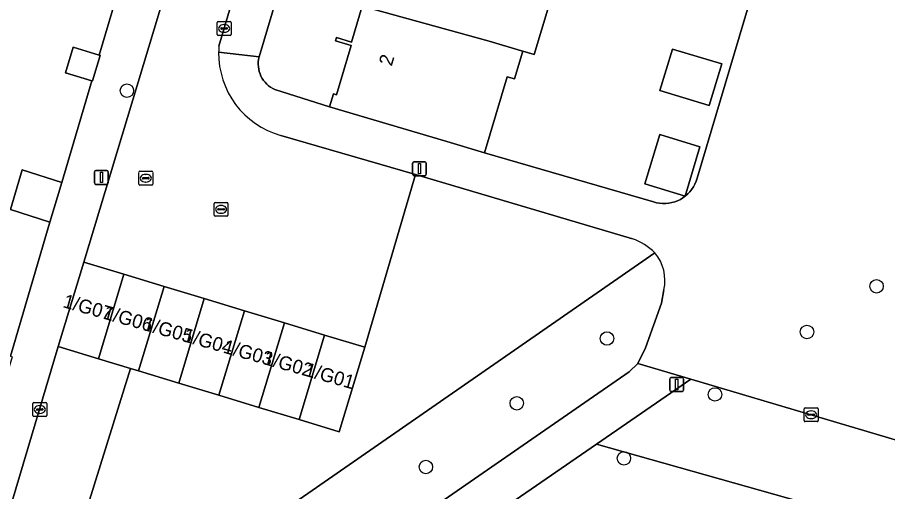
# Model space of a CAD drawing. Extents: x 162184 to 163154, y 385507 to 386516.
# Drawn here: x 162712.4 to 162775.6, y 386055 to 386089.3 of the extents above; entities that cross this region are included whole.
import ezdxf

# ---------------------------------------------------------------- set-up
doc = ezdxf.new("R2010")
doc.units = 0
for name, color, linetype in [('IMGEO_Boom', 7, 'Continuous'), ('IMGEO_Erf', 7, 'Continuous'), ('IMGEO_Groenvoorziening', 7, 'Continuous'), ('IMGEO_Kolk', 7, 'Continuous'), ('IMGEO_Lichtmast', 7, 'Continuous'), ('IMGEO_Pand', 7, 'Continuous'), ('IMGEO_Pand_nummerreeks', 7, 'Continuous'), ('IMGEO_Rijbaan_lokaal_open', 7, 'Continuous'), ('IMGEO_Rioolput', 7, 'Continuous'), ('IMGEO_Voetpad_halfverhard', 7, 'Continuous'), ('IMGEO_Voetpad_open', 7, 'Continuous')]:
    doc.layers.add(name, color=color, linetype=linetype)

msp = doc.modelspace()

# ---------------------------------------------------------------- linework, layer by layer
at = {"layer": 'IMGEO_Boom'}
for centre in [(162720.367, 386084.025), (162774.757, 386069.847), (162769.709, 386066.539), (162755.197, 386066.062), (162763.033, 386062.009), (162748.653, 386061.368), (162756.426, 386057.379), (162742.059, 386056.751)]:
    msp.add_circle(centre, 0.489, dxfattribs=at)
at = {"layer": 'IMGEO_Erf'}
for points in [[(162748.726, 386149.462), (162729.962, 386086.464), (162729.923, 386086.29), (162729.9, 386086.113), (162729.893, 386085.934), (162729.902, 386085.756), (162729.927, 386085.579), (162729.967, 386085.406), (162730.023, 386085.236), (162730.093, 386085.072), (162730.178, 386084.915), (162730.277, 386084.766), (162730.389, 386084.627), (162730.512, 386084.498), (162730.647, 386084.381), (162730.791, 386084.277), (162730.945, 386084.185), (162731.096, 386084.112), (162735.074, 386082.862), (162735.351, 386083.791), (162735.572, 386083.726), (162736.634, 386087.29), (162735.49, 386087.63), (162735.563, 386087.875), (162736.667, 386087.546), (162737.443, 386090.149)], [(162751.517, 386091.957), (162749.91, 386086.652), (162749.086, 386086.882), (162748.488, 386084.875), (162747.961, 386085.032), (162746.315, 386079.512), (162758.579, 386075.961), (162758.794, 386075.903), (162759.013, 386075.865), (162759.235, 386075.846), (162759.457, 386075.847), (162759.679, 386075.868), (162759.898, 386075.909), (162760.112, 386075.969), (162760.32, 386076.049), (162760.52, 386076.146), (162760.711, 386076.261), (162760.89, 386076.392), (162761.057, 386076.539), (162761.211, 386076.7), (162761.349, 386076.875), (162761.471, 386077.061), (162761.576, 386077.257), (162761.663, 386077.462), (162761.733, 386077.677), (162769.446, 386103.583)], [(162714.781, 386074.502), (162711.92, 386075.404), (162712.775, 386078.28), (162715.637, 386077.378), (162717.814, 386084.744), (162715.905, 386085.309), (162716.455, 386087.166), (162718.363, 386086.601), (162721.377, 386096.799)], [(162703.157, 386035.017), (162711.228, 386062.433), (162709.084, 386063.069), (162709.779, 386065.415), (162711.919, 386064.781), (162714.781, 386074.502)]]:
    msp.add_lwpolyline(points, dxfattribs=at)
for points in [[(162763.522, 386085.955), (162762.609, 386082.944), (162759.03, 386084.029), (162759.942, 386087.04)], [(162761.944, 386079.957), (162760.862, 386076.386), (162757.947, 386077.269), (162759.029, 386080.84)]]:
    msp.add_lwpolyline(points, close=True, dxfattribs=at)
at = {"layer": 'IMGEO_Groenvoorziening'}
for points in [[(162757.052, 386073.289), (162741.294, 386077.935), (162737.62, 386065.425), (162735.767, 386059.304), (162732.856, 386060.186), (162729.945, 386061.067), (162727.034, 386061.948), (162724.123, 386062.83), (162721.212, 386063.711), (162720.628, 386063.888), (162714.555, 386044.411), (162717.31, 386043.615), (162758.68, 386072.273)], [(162758.68, 386072.273), (162717.31, 386043.615), (162714.555, 386044.411), (162720.628, 386063.888), (162718.301, 386064.593), (162715.39, 386065.474), (162705.881, 386033.637)], [(162756.796, 386063.642), (162757.426, 386064.259), (162757.996, 386065.377), (162759.153, 386068.627), (162759.328, 386069.587)], [(162707.08, 386031.526), (162707.413, 386031.401), (162707.756, 386031.307), (162708.106, 386031.243), (162708.46, 386031.211), (162708.816, 386031.211), (162709.17, 386031.242), (162709.52, 386031.305), (162709.863, 386031.4), (162710.196, 386031.524), (162710.517, 386031.677), (162710.65, 386031.752), (162756.796, 386063.642)]]:
    msp.add_lwpolyline(points, dxfattribs=at)
for points in [[(162784.669, 386056.18), (162761.276, 386063.106), (162754.435, 386058.403), (162786.142, 386049.469), (162786.962, 386052.186), (162787.099, 386053.344), (162787.091, 386053.575), (162787.062, 386053.805), (162787.012, 386054.031), (162786.943, 386054.251), (162786.854, 386054.465), (162786.746, 386054.67), (162786.621, 386054.864), (162786.479, 386055.046), (162786.445, 386055.085), (162785.618, 386055.732)], [(162786.142, 386049.469), (162754.435, 386058.403), (162737.255, 386046.591), (162738.48, 386044.772), (162728.34, 386033.438), (162739.19, 386030.113), (162741.29, 386037.011), (162742.152, 386036.767), (162746.108, 386049.727), (162752.73, 386047.547), (162754.611, 386053.744), (162757.507, 386052.864), (162760.403, 386051.985), (162763.299, 386051.105), (162766.195, 386050.226), (162769.092, 386049.346), (162771.988, 386048.466), (162774.884, 386047.587), (162777.78, 386046.707), (162780.676, 386045.828), (162783.572, 386044.948), (162781.69, 386038.751), (162782.799, 386038.397)]]:
    msp.add_lwpolyline(points, close=True, dxfattribs=at)
for centre, radius, start, end in [((162755.533, 386069.043), 4.509, 45.74708, 70.31811), ((162756.263, 386070.269), 3.14, 347.45747, 39.6695)]:
    msp.add_arc(centre, radius, start, end, dxfattribs=at)
at = {"layer": 'IMGEO_Kolk'}
for p, q in [((162726.92, 386088.104), (162726.92, 386088.956)), ((162726.995, 386089.03), (162727.847, 386089.03)), ((162727.408, 386088.81), (162727.433, 386088.81)), ((162727.921, 386088.956), (162727.921, 386088.104)), ((162727.179, 386088.524), (162727.179, 386088.536)), ((162727.617, 386088.487), (162727.219, 386088.487)), ((162727.222, 386088.573), (162727.62, 386088.573)), ((162727.431, 386088.25), (162727.406, 386088.25)), ((162727.663, 386088.536), (162727.663, 386088.524)), ((162727.847, 386088.03), (162726.995, 386088.03)), ((162726.698, 386074.995), (162726.698, 386075.847)), ((162726.773, 386075.921), (162727.625, 386075.921)), ((162727.186, 386075.701), (162727.211, 386075.701)), ((162727.699, 386075.847), (162727.699, 386074.995)), ((162727.625, 386074.921), (162726.773, 386074.921)), ((162726.957, 386075.415), (162726.957, 386075.427)), ((162727.395, 386075.378), (162726.997, 386075.378)), ((162727, 386075.464), (162727.398, 386075.464)), ((162727.209, 386075.141), (162727.184, 386075.141)), ((162727.441, 386075.427), (162727.441, 386075.415)), ((162713.547, 386060.492), (162713.547, 386061.344)), ((162713.622, 386061.418), (162714.474, 386061.418)), ((162714.035, 386061.198), (162714.06, 386061.198)), ((162714.548, 386061.344), (162714.548, 386060.492)), ((162769.585, 386061.038), (162770.437, 386061.038)), ((162714.474, 386060.418), (162713.622, 386060.418)), ((162713.806, 386060.912), (162713.806, 386060.924)), ((162714.244, 386060.875), (162713.846, 386060.875)), ((162713.849, 386060.961), (162714.247, 386060.961)), ((162714.058, 386060.638), (162714.033, 386060.638)), ((162714.29, 386060.924), (162714.29, 386060.912)), ((162769.51, 386060.112), (162769.51, 386060.964)), ((162769.769, 386060.532), (162769.769, 386060.544)), ((162770.207, 386060.495), (162769.809, 386060.495)), ((162769.812, 386060.581), (162770.21, 386060.581)), ((162769.998, 386060.818), (162770.023, 386060.818)), ((162770.253, 386060.544), (162770.253, 386060.532)), ((162770.511, 386060.964), (162770.511, 386060.112)), ((162770.437, 386060.038), (162769.585, 386060.038)), ((162770.021, 386060.258), (162769.996, 386060.258))]:
    msp.add_line(p, q, dxfattribs=at)
for points in [[(162726.92, 386088.104), (162726.92, 386088.956)], [(162726.995, 386089.03), (162727.847, 386089.03)], [(162727.921, 386088.956), (162727.921, 386088.104)], [(162727.847, 386088.03), (162726.995, 386088.03)], [(162726.698, 386074.995), (162726.698, 386075.847)], [(162726.773, 386075.921), (162727.625, 386075.921)], [(162727.699, 386075.847), (162727.699, 386074.995)], [(162727.625, 386074.921), (162726.773, 386074.921)], [(162713.547, 386060.492), (162713.547, 386061.344)], [(162713.622, 386061.418), (162714.474, 386061.418)], [(162714.548, 386061.344), (162714.548, 386060.492)], [(162769.585, 386061.038), (162770.437, 386061.038)], [(162714.474, 386060.418), (162713.622, 386060.418)], [(162769.51, 386060.112), (162769.51, 386060.964)], [(162770.511, 386060.964), (162770.511, 386060.112)], [(162770.437, 386060.038), (162769.585, 386060.038)]]:
    msp.add_lwpolyline(points, dxfattribs=at)
for centre, radius, start, end in [((162726.997, 386088.954), 0.0765, 91.55205, 178.44795), ((162726.997, 386088.954), 0.0765, 91.55205, 178.44795), ((162727.845, 386088.954), 0.0765, 1.55205, 88.44795), ((162727.845, 386088.954), 0.0765, 1.55205, 88.44795), ((162727.219, 386088.533), 0.0403, 85.87752, 175.75265), ((162727.216, 386088.523), 0.0366, 178.93798, 274.71019), ((162727.62, 386088.53), 0.043, 264.86636, 352.45326), ((162727.624, 386088.535), 0.0386, 1.73085, 96.63898), ((162726.997, 386088.106), 0.0765, 181.55205, 268.44795), ((162726.997, 386088.106), 0.0765, 181.55205, 268.44795), ((162727.845, 386088.106), 0.0765, 271.55205, 358.44795), ((162727.845, 386088.106), 0.0765, 271.55205, 358.44795), ((162726.775, 386075.845), 0.0765, 91.55205, 178.44795), ((162726.775, 386075.845), 0.0765, 91.55205, 178.44795), ((162727.623, 386075.845), 0.0765, 1.55205, 88.44795), ((162727.623, 386075.845), 0.0765, 1.55205, 88.44795), ((162726.775, 386074.997), 0.0765, 181.55205, 268.44795), ((162726.775, 386074.997), 0.0765, 181.55205, 268.44795), ((162726.997, 386075.424), 0.0403, 85.87752, 175.75265), ((162726.994, 386075.414), 0.0366, 178.93798, 274.71019), ((162727.398, 386075.421), 0.043, 264.86636, 352.45326), ((162727.402, 386075.426), 0.0386, 1.73085, 96.63898), ((162727.623, 386074.997), 0.0765, 271.55205, 358.44795), ((162727.623, 386074.997), 0.0765, 271.55205, 358.44795), ((162713.624, 386061.342), 0.0765, 91.55205, 178.44795), ((162713.624, 386061.342), 0.0765, 91.55205, 178.44795), ((162714.472, 386061.342), 0.0765, 1.55205, 88.44795), ((162714.472, 386061.342), 0.0765, 1.55205, 88.44795), ((162769.587, 386060.962), 0.0765, 91.55205, 178.44795), ((162769.587, 386060.962), 0.0765, 91.55205, 178.44795), ((162770.435, 386060.962), 0.0765, 1.55205, 88.44795), ((162770.435, 386060.962), 0.0765, 1.55205, 88.44795), ((162713.624, 386060.494), 0.0765, 181.55205, 268.44795), ((162713.624, 386060.494), 0.0765, 181.55205, 268.44795), ((162713.846, 386060.921), 0.0403, 85.87752, 175.75265), ((162713.843, 386060.911), 0.0366, 178.93798, 274.71019), ((162714.247, 386060.918), 0.043, 264.86636, 352.45326), ((162714.251, 386060.923), 0.0386, 1.73085, 96.63898), ((162714.472, 386060.494), 0.0765, 271.55205, 358.44795), ((162714.472, 386060.494), 0.0765, 271.55205, 358.44795), ((162769.809, 386060.541), 0.0403, 85.87752, 175.75265), ((162769.806, 386060.531), 0.0366, 178.93798, 274.71019), ((162770.21, 386060.538), 0.043, 264.86636, 352.45326), ((162770.214, 386060.543), 0.0386, 1.73085, 96.63898), ((162769.587, 386060.114), 0.0765, 181.55205, 268.44795), ((162769.587, 386060.114), 0.0765, 181.55205, 268.44795), ((162770.435, 386060.114), 0.0765, 271.55205, 358.44795), ((162770.435, 386060.114), 0.0765, 271.55205, 358.44795)]:
    msp.add_arc(centre, radius, start, end, dxfattribs=at)
for centre, major_axis, ratio, start_param, end_param in [((162727.407, 386088.53), (-0.387, 0.002), 0.722429, 4.712389, 7.853982), ((162727.432, 386088.53), (-0.39, 0.002), 0.717154, 1.570796, 4.712389), ((162727.185, 386075.421), (-0.387, 0.002), 0.722429, 4.712389, 7.853982), ((162727.21, 386075.421), (-0.39, 0.002), 0.717154, 1.570796, 4.712389), ((162714.034, 386060.918), (-0.387, 0.002), 0.722429, 4.712389, 7.853982), ((162714.059, 386060.918), (-0.39, 0.002), 0.717154, 1.570796, 4.712389), ((162769.997, 386060.538), (-0.387, 0.002), 0.722429, 4.712389, 7.853982), ((162770.022, 386060.538), (-0.39, 0.002), 0.717154, 1.570796, 4.712389)]:
    msp.add_ellipse(centre, major_axis=major_axis, ratio=ratio, start_param=start_param, end_param=end_param, dxfattribs=at)
at = {"layer": 'IMGEO_Lichtmast'}
for p, q in [((162741.095, 386077.961), (162741.095, 386078.761)), ((162741.095, 386078.761), (162741.095, 386077.961)), ((162741.195, 386078.861), (162741.985, 386078.861)), ((162741.985, 386078.861), (162741.195, 386078.861)), ((162742.085, 386078.761), (162742.085, 386077.961)), ((162742.085, 386077.961), (162742.085, 386078.761)), ((162718.02, 386077.334), (162718.02, 386078.134)), ((162718.02, 386078.134), (162718.02, 386077.334)), ((162718.12, 386078.234), (162718.91, 386078.234)), ((162718.91, 386078.234), (162718.12, 386078.234)), ((162719.01, 386078.134), (162719.01, 386077.334)), ((162719.01, 386077.334), (162719.01, 386078.134)), ((162741.985, 386077.861), (162741.195, 386077.861)), ((162741.195, 386077.861), (162741.985, 386077.861)), ((162718.91, 386077.234), (162718.12, 386077.234)), ((162718.12, 386077.234), (162718.91, 386077.234)), ((162759.76, 386062.329), (162759.76, 386063.129)), ((162759.76, 386063.129), (162759.76, 386062.329)), ((162759.86, 386063.229), (162760.65, 386063.229)), ((162760.65, 386063.229), (162759.86, 386063.229)), ((162760.75, 386063.129), (162760.75, 386062.329)), ((162760.75, 386062.329), (162760.75, 386063.129)), ((162760.65, 386062.229), (162759.86, 386062.229)), ((162759.86, 386062.229), (162760.65, 386062.229))]:
    msp.add_line(p, q, dxfattribs=at)
for points in [[(162741.515, 386078.736), (162741.665, 386078.736), (162741.665, 386077.986), (162741.515, 386077.986), (162741.515, 386078.736)], [(162718.44, 386078.109), (162718.59, 386078.109), (162718.59, 386077.359), (162718.44, 386077.359), (162718.44, 386078.109)], [(162760.18, 386063.104), (162760.33, 386063.104), (162760.33, 386062.354), (162760.18, 386062.354), (162760.18, 386063.104)]]:
    msp.add_lwpolyline(points, dxfattribs=at)
for centre, start, end in [((162741.195, 386078.761), 90, 180), ((162741.195, 386078.761), 90, 180), ((162741.985, 386078.761), 0, 90), ((162741.985, 386078.761), 360, 90), ((162718.12, 386078.134), 90, 180), ((162718.12, 386078.134), 90, 180), ((162718.91, 386078.134), 0, 90), ((162718.91, 386078.134), 360, 90), ((162741.195, 386077.961), 180, 270), ((162741.195, 386077.961), 180, 270), ((162741.985, 386077.961), 270, 0), ((162741.985, 386077.961), 270, 0), ((162718.12, 386077.334), 180, 270), ((162718.12, 386077.334), 180, 270), ((162718.91, 386077.334), 270, 0), ((162718.91, 386077.334), 270, 0), ((162759.86, 386063.129), 90, 180), ((162759.86, 386063.129), 90, 180), ((162760.65, 386063.129), 0, 90), ((162760.65, 386063.129), 360, 90), ((162759.86, 386062.329), 180, 270), ((162759.86, 386062.329), 180, 270), ((162760.65, 386062.329), 270, 0), ((162760.65, 386062.329), 270, 0)]:
    msp.add_arc(centre, 0.1, start, end, dxfattribs=at)
at = {"layer": 'IMGEO_Pand'}
for points in [[(162754.46, 386093.36), (162752.141, 386094.051), (162747.794, 386095.346), (162740.655, 386097.299), (162738.746, 386090.892), (162738.575, 386090.943), (162738.336, 386090.144), (162736.371, 386090.729), (162736.3, 386090.49), (162737.443, 386090.149), (162746.654, 386087.61), (162748.993, 386086.91), (162749.086, 386086.882), (162749.91, 386086.652), (162751.517, 386091.957), (162753.838, 386091.271)], [(162746.315, 386079.512), (162747.961, 386085.032), (162748.488, 386084.875), (162749.086, 386086.882), (162748.993, 386086.91), (162746.654, 386087.61), (162737.443, 386090.149), (162736.667, 386087.546), (162735.563, 386087.875), (162735.49, 386087.63), (162736.634, 386087.29), (162735.572, 386083.726), (162735.351, 386083.791), (162735.074, 386082.862), (162743.573, 386080.329)], [(162718.363, 386086.601), (162716.455, 386087.166), (162715.905, 386085.309), (162717.814, 386084.744), (162717.88, 386084.724), (162718.43, 386086.581)], [(162759.03, 386084.029), (162762.609, 386082.944), (162763.522, 386085.955), (162759.942, 386087.04)], [(162757.947, 386077.269), (162760.862, 386076.386), (162761.944, 386079.957), (162759.029, 386080.84)], [(162715.637, 386077.378), (162712.775, 386078.28), (162711.92, 386075.404), (162714.781, 386074.502)], [(162715.39, 386065.474), (162718.301, 386064.593), (162720.154, 386070.714), (162717.243, 386071.595)], [(162720.154, 386070.714), (162718.301, 386064.593), (162720.628, 386063.888), (162721.212, 386063.711), (162723.065, 386069.832)], [(162723.065, 386069.832), (162721.212, 386063.711), (162724.123, 386062.83), (162725.976, 386068.951)], [(162725.976, 386068.951), (162724.123, 386062.83), (162727.034, 386061.948), (162728.887, 386068.069)], [(162728.887, 386068.069), (162727.034, 386061.948), (162729.945, 386061.067), (162731.798, 386067.188)], [(162731.798, 386067.188), (162729.945, 386061.067), (162732.856, 386060.186), (162734.709, 386066.306)], [(162734.709, 386066.306), (162732.856, 386060.186), (162735.767, 386059.304), (162737.62, 386065.425)]]:
    msp.add_lwpolyline(points, close=True, dxfattribs=at)
at = {"layer": 'IMGEO_Rijbaan_lokaal_open'}
for points in [[(162735.486, 386115.734), (162730.846, 386117.114), (162725.891, 386100.255), (162717.243, 386071.595), (162720.154, 386070.714), (162723.065, 386069.832), (162725.976, 386068.951), (162728.887, 386068.069), (162731.798, 386067.188), (162734.709, 386066.306), (162737.62, 386065.425), (162741.294, 386077.935), (162731.535, 386080.772)], [(162727.044, 386087.256), (162730.41, 386098.664), (162735.486, 386115.734)], [(162769.446, 386103.583), (162761.733, 386077.677), (162761.663, 386077.462), (162761.576, 386077.257), (162761.471, 386077.061), (162761.349, 386076.875), (162761.211, 386076.7), (162761.057, 386076.539), (162760.89, 386076.392), (162760.711, 386076.261), (162760.52, 386076.146), (162760.32, 386076.049), (162760.112, 386075.969), (162759.898, 386075.909), (162759.679, 386075.868), (162759.457, 386075.847), (162759.235, 386075.846), (162759.013, 386075.865), (162758.794, 386075.903), (162758.579, 386075.961), (162746.315, 386079.512), (162743.573, 386080.329), (162735.074, 386082.862), (162731.096, 386084.112), (162730.945, 386084.185), (162730.791, 386084.277), (162730.647, 386084.381), (162730.512, 386084.498), (162730.389, 386084.627), (162730.277, 386084.766), (162730.178, 386084.915), (162730.093, 386085.072), (162730.023, 386085.236), (162729.967, 386085.406), (162729.927, 386085.579), (162729.902, 386085.756), (162729.893, 386085.934), (162729.9, 386086.113), (162729.923, 386086.29), (162729.962, 386086.464), (162727.023, 386086.818)], [(162731.535, 386080.772), (162741.294, 386077.935), (162757.052, 386073.289)], [(162759.328, 386069.587), (162759.153, 386068.627), (162757.996, 386065.377), (162757.426, 386064.259), (162761.276, 386063.106), (162784.669, 386056.18), (162784.356, 386059.006)]]:
    msp.add_lwpolyline(points, dxfattribs=at)
for centre, radius, start, end in [((162732.373, 386086.781), 5.35, 174.90615, 179.60394), ((162733.219, 386086.736), 6.197, 179.23909, 254.22729), ((162733.219, 386086.736), 6.197, 179.23909, 254.22729), ((162755.533, 386069.043), 4.509, 45.74708, 70.31811), ((162756.263, 386070.269), 3.14, 347.45747, 39.6695)]:
    msp.add_arc(centre, radius, start, end, dxfattribs=at)
at = {"layer": 'IMGEO_Rioolput'}
for p, q in [((162721.237, 386077.252), (162721.237, 386078.104)), ((162721.312, 386078.178), (162722.164, 386078.178)), ((162722.238, 386078.104), (162722.238, 386077.252)), ((162721.496, 386077.672), (162721.496, 386077.684)), ((162721.934, 386077.635), (162721.536, 386077.635)), ((162721.539, 386077.721), (162721.937, 386077.721)), ((162721.725, 386077.958), (162721.75, 386077.958)), ((162721.98, 386077.684), (162721.98, 386077.672)), ((162722.164, 386077.178), (162721.312, 386077.178)), ((162721.748, 386077.398), (162721.723, 386077.398))]:
    msp.add_line(p, q, dxfattribs=at)
for points in [[(162721.237, 386077.252), (162721.237, 386078.104)], [(162721.312, 386078.178), (162722.164, 386078.178)], [(162722.238, 386078.104), (162722.238, 386077.252)], [(162722.164, 386077.178), (162721.312, 386077.178)]]:
    msp.add_lwpolyline(points, dxfattribs=at)
for centre, radius, start, end in [((162721.314, 386078.102), 0.0765, 91.55205, 178.44795), ((162721.314, 386078.102), 0.0765, 91.55205, 178.44795), ((162722.162, 386078.102), 0.0765, 1.55205, 88.44795), ((162722.162, 386078.102), 0.0765, 1.55205, 88.44795), ((162721.536, 386077.681), 0.0403, 85.87752, 175.75265), ((162721.533, 386077.671), 0.0366, 178.93798, 274.71019), ((162721.937, 386077.678), 0.043, 264.86636, 352.45326), ((162721.941, 386077.683), 0.0386, 1.73085, 96.63898), ((162721.314, 386077.254), 0.0765, 181.55205, 268.44795), ((162721.314, 386077.254), 0.0765, 181.55205, 268.44795), ((162722.162, 386077.254), 0.0765, 271.55205, 358.44795), ((162722.162, 386077.254), 0.0765, 271.55205, 358.44795)]:
    msp.add_arc(centre, radius, start, end, dxfattribs=at)
for centre, major_axis, ratio, start_param, end_param in [((162721.724, 386077.678), (-0.387, 0.002), 0.722429, 4.712389, 7.853982), ((162721.749, 386077.678), (-0.39, 0.002), 0.717154, 1.570796, 4.712389)]:
    msp.add_ellipse(centre, major_axis=major_axis, ratio=ratio, start_param=start_param, end_param=end_param, dxfattribs=at)
at = {"layer": 'IMGEO_Voetpad_halfverhard'}
msp.add_lwpolyline([(162682.675, 386008.885), (162718.056, 386033.343), (162721.276, 386035.605), (162737.255, 386046.591), (162754.435, 386058.403), (162761.276, 386063.106), (162757.426, 386064.259), (162756.796, 386063.642), (162710.65, 386031.752), (162702.847, 386026.374), (162680.247, 386010.788), (162676.196, 386007.994)], dxfattribs=at)
at = {"layer": 'IMGEO_Voetpad_open'}
for points in [[(162757.217, 386188.564), (162747.844, 386157.099), (162747.828, 386157.024), (162745.815, 386150.242), (162745.775, 386150.139), (162742.241, 386138.459), (162739.071, 386127.769), (162739.041, 386127.618), (162735.989, 386117.426), (162735.486, 386115.734), (162730.41, 386098.664), (162727.044, 386087.256)], [(162727.023, 386086.818), (162729.962, 386086.464), (162748.726, 386149.462), (162748.746, 386149.525), (162750.699, 386156.134), (162751.879, 386160.019), (162753.736, 386166.228), (162758.04, 386180.591)], [(162705.881, 386033.637), (162715.39, 386065.474), (162717.243, 386071.595), (162725.891, 386100.255), (162730.846, 386117.114)], [(162723.787, 386104.88), (162721.438, 386096.954), (162721.377, 386096.799), (162718.363, 386086.601), (162718.43, 386086.581), (162717.88, 386084.724), (162717.814, 386084.744), (162715.637, 386077.378), (162714.781, 386074.502), (162711.919, 386064.781), (162712.041, 386064.745), (162711.346, 386062.398), (162711.228, 386062.433), (162703.157, 386035.017)]]:
    msp.add_lwpolyline(points, dxfattribs=at)
msp.add_arc((162732.373, 386086.781), 5.35, 174.90615, 179.60394, dxfattribs=at)

# ---------------------------------------------------------------- texts
at = {"layer": 'IMGEO_Pand_nummerreeks'}
for s, rotation, p in [('2', 73.75932, (162739.579, 386085.753)), ('1/G07', 344.19031, (162715.662, 386068.342)), ('1/G06', 344.19031, (162718.569, 386067.52)), ('1/G05', 344.19031, (162721.475, 386066.697)), ('1/G04', 344.19031, (162724.381, 386065.874)), ('1/G03', 344.19031, (162727.287, 386065.051)), ('1/G02', 344.19031, (162730.188, 386064.23)), ('1/G01', 344.19031, (162733.206, 386063.375))]:
    msp.add_text(s, height=1, rotation=rotation, dxfattribs=at).set_placement(p)

doc.saveas('drawing.dxf')
